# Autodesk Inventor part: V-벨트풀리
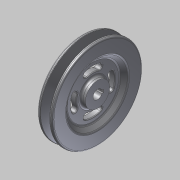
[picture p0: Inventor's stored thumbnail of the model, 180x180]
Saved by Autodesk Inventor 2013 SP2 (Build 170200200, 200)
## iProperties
Created: 2015-12
Part Number: V-벨트풀리
Document SubType Name: Modeling
Designer: mdu
Density: 8.08 g/cm^3
Material: 스테인리스강
Author: mdu
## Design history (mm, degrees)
sketch "스케치1"
  geometry: L1 (-10, 0)-(10, 0); L2 (-10, 0)-(-10, 16); L3 (-10, 16)-(-4, 16); L4 (-4, 16)-(-4, 35); L5 (-4, 35)-(-10, 41); L6 (-10, 41)-(-10, 59.5); L7 (-10, 59.5)-(-6.062, 59.5); L8 (-6.062, 59.5)-(-2.001, 47); L9 (-2.001, 47)-(2.001, 47); L10 (2.001, 47)-(6.062, 59.5); L11 (6.062, 59.5)-(10, 59.5); L12 (10, 59.5)-(10, 41); L13 (10, 41)-(4, 35); L14 (4, 35)-(4, 16); L15 (4, 16)-(10, 16); L16 (10, 16)-(10, 0); L17 (-4.6, 55)-(4.6, 55); 2 further points
  constraints: 34 end point, 7 parallel, 6 equal length, 5 collinear, 3 perpendicular, 2 point on line, 1 coincident, 1 horizontal, 1 midpoint
  dimensions: "d0" = 20 distance of L1.start L1.end; "d1" = 9.2 distance of L17.start L17.end; "d2" = 36 deg angle of L10 L8; "d3" = 4.5 distance between parallel lines of L7 L17; "d4" = 8 distance between parallel lines of L9 L17; "d6" = 110 diameter of L17 L1; "d7" = 32 diameter of L3 L1; "d8" = 82 diameter of L5.end L1; "d9" = 6 distance of L2.end L3.end; "d10" = 135 deg angle of L4 L5
revolve "회전1" sketch "스케치1" stored, may be unused: angle "d11" = 90 deg
fillet "모깎기1" dims "d12" = 2, "d13" = 0.5, "d14" = 1, "d15" = 3
sketch "스케치2"
  geometry: L1 (-2, 5.657)-(-2, 7.8); L2 (-2, 7.8)-(2, 7.8); L3 (2, 7.8)-(2, 5.657); A1 r 6 centre (0, 0) between (-2, 5.657) and (2, 5.657); 1 further point
  constraints: 6 end point, 2 parallel, 2 point on circle, 1 centre point, 1 coincident, 1 perpendicular, 1 vertical
  dimensions: "d16" = 12 diameter of A1; "d17" = 4 distance of L1.end L2.end; "d18" = 13.8 dimension on A1 L2 (computed from d16)
extrude "돌출1" cut sketch "스케치2" stored distance "d19" = 10; taper "d20" = 0 deg
sketch "스케치3"
  geometry: L1 (0, 0)-(0, 25.5); L2 (0, 0)-(-8.722, 23.962); C1 r 33.757 at (0, 0) reference; C2 r 19 at (0, 0) reference; A1 r 25.5 centre (0, 0) between (0, 25.5) and (-8.722, 23.962); A2 r 3.5 centre (-8.722, 23.962) between (-9.919, 27.251) and (-7.524, 20.673); A3 r 3.5 centre (8.722, 23.962) between (7.524, 20.673) and (9.919, 27.251); A4 r 29 centre (0, 0) between (9.919, 27.251) and (-9.919, 27.251); A5 r 22 centre (0, 0) between (7.524, 20.673) and (-7.524, 20.673); 1 further point
  constraints: 10 point on circle, 5 centre point, 4 coincident, 4 end point, 1 point on line, 1 symmetric about line, 1 tangent, 1 vertical, 1 other
  dimensions: "d24" = 51 diameter of A1; "d27" = 20 deg angle of L1 L2; "d29" = 7 diameter of A2
extrude "돌출2" cut sketch "스케치3" stored distance "d30" = 10; taper "d31" = 0 deg
fillet "모깎기2" dims "d32" = 1
node "솔리드1"
pattern_circular "원형 패턴1" dims angle "d34" = 360 deg
